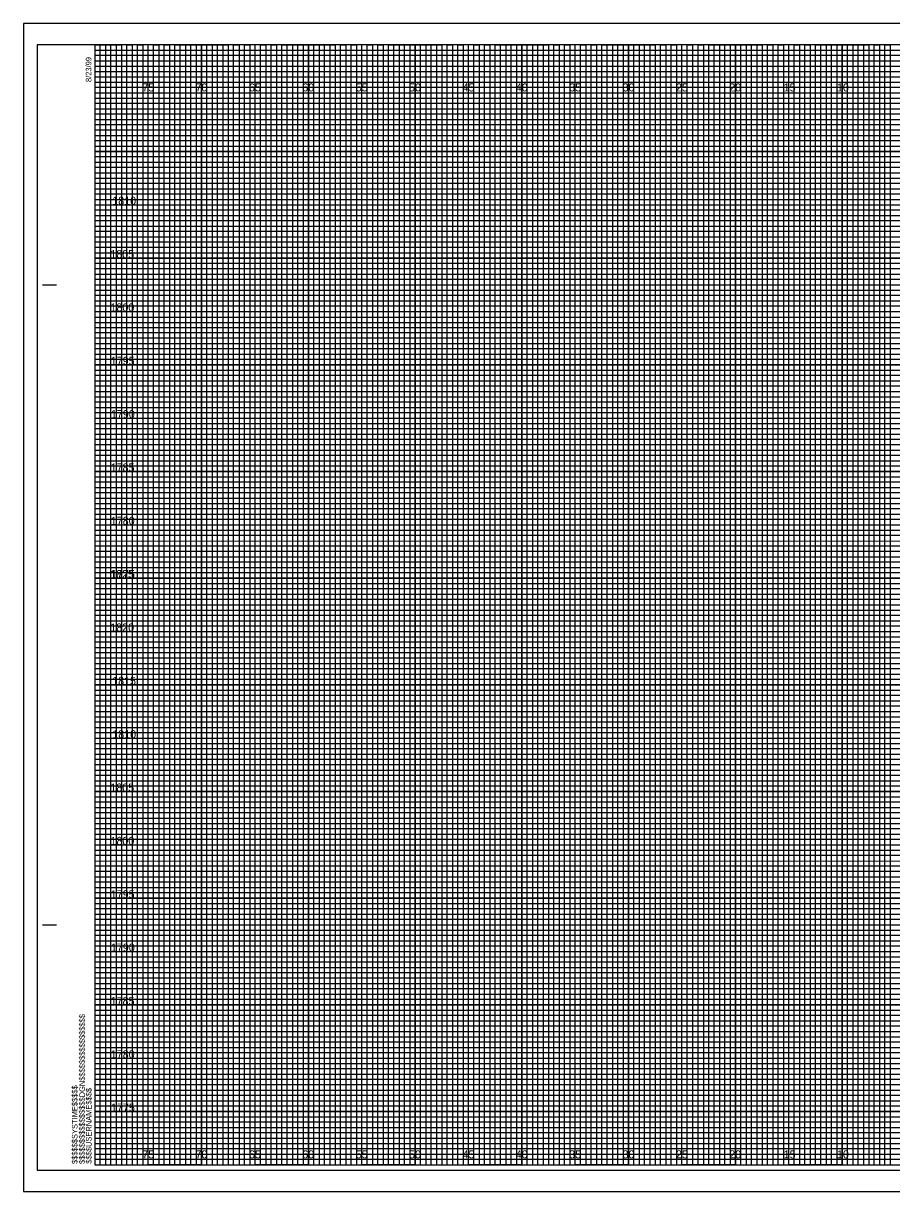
# Model space of a CAD drawing. Extents: x -7 to 162, y -2 to 107.
# Drawn here: x -6.7 to 74.6, y -2.5 to 107 of the extents above; entities that cross this region are included whole.
import ezdxf

# ---------------------------------------------------------------- set-up
doc = ezdxf.new("R2010")
doc.units = 0
for name, color, linetype in [('Prop XS Elevation Labels', 7, 'Continuous'), ('Prop XS Offset Labels', 7, 'Continuous'), ('Sheet Cross Section CELL', 7, 'Continuous'), ('Sheet Cross Section Grid Major CELL', 7, 'Continuous'), ('Sheet Cross Section Grid Middle CELL', 7, 'Continuous'), ('Sheet Cross Section Grid Minor 1 CELL', 7, 'Continuous'), ('Sheet Cross Section Grid Minor 2 CELL', 7, 'Continuous'), ('Sheet Cutting Line CELL', 7, 'Continuous'), ('Sheet DOT Grid CELL', 7, 'Continuous'), ('Sheet Plot Border Inside CELL', 7, 'Continuous'), ('Sheet Plot Border Outside CELL', 7, 'Continuous')]:
    doc.layers.add(name, color=color, linetype=linetype)

msp = doc.modelspace()

# ---------------------------------------------------------------- linework, layer by layer
at = {"layer": 'Sheet Cross Section CELL'}
for p, q in [((-4.9, 82.5), (-3.65, 82.5)), ((-4.85, 82.5), (-3.6, 82.5)), ((-4.9, 22.5), (-3.65, 22.5)), ((-4.85, 22.5), (-3.6, 22.5)), ((0, 0), (0, 0)), ((0, 0), (0, 0)), ((0, 0), (0, 0)), ((0, 0), (0, 0)), ((0, 0), (0, 0)), ((0, 0), (0, 0)), ((0, 0), (0, 0))]:
    msp.add_line(p, q, dxfattribs=at)
msp.add_lwpolyline([(160, 105), (0, 105), (0, 0), (160, 0)], close=True, dxfattribs=at)
at = {"layer": 'Sheet Cross Section Grid Major CELL'}
for p, q in [((5, 105), (0, 105)), ((5, 0), (5, 105)), ((15, 105), (10, 105)), ((10, 105), (10, 0)), ((15, 0), (15, 105)), ((25, 105), (20, 105)), ((20, 105), (20, 0)), ((25, 0), (25, 105)), ((35, 105), (30, 105)), ((30, 105), (30, 0)), ((35, 0), (35, 105)), ((45, 105), (40, 105)), ((40, 105), (40, 0)), ((45, 0), (45, 105)), ((55, 105), (50, 105)), ((50, 105), (50, 0)), ((55, 0), (55, 105)), ((65, 105), (60, 105)), ((60, 105), (60, 0)), ((65, 0), (65, 105)), ((75, 105), (70, 105)), ((70, 105), (70, 0)), ((10, 0), (5, 0)), ((20, 0), (15, 0)), ((30, 0), (25, 0)), ((40, 0), (35, 0)), ((50, 0), (45, 0)), ((60, 0), (55, 0)), ((70, 0), (65, 0))]:
    msp.add_line(p, q, dxfattribs=at)
for points in [[(0, 100), (160, 100), (160, 95), (0, 95)], [(0, 90), (160, 90), (160, 85), (0, 85)], [(0, 80), (160, 80), (160, 75), (0, 75)], [(0, 70), (160, 70), (160, 65), (0, 65)], [(0, 60), (160, 60), (160, 55), (0, 55)], [(0, 50), (160, 50), (160, 45), (0, 45)], [(0, 40), (160, 40), (160, 35), (0, 35)], [(0, 30), (160, 30), (160, 25), (0, 25)], [(0, 20), (160, 20), (160, 15), (0, 15)], [(0, 10), (160, 10), (160, 5), (0, 5)]]:
    msp.add_lwpolyline(points, dxfattribs=at)
at = {"layer": 'Sheet Cross Section Grid Middle CELL'}
for points in [[(0, 105), (2.5, 105), (2.5, 0), (7.5, 0), (7.5, 105), (12.5, 105), (12.5, 0), (17.5, 0), (17.5, 105), (22.5, 105), (22.5, 0), (27.5, 0), (27.5, 105), (32.5, 105), (32.5, 0), (37.5, 0), (37.5, 105), (42.5, 105), (42.5, 0), (47.5, 0), (47.5, 105), (52.5, 105), (52.5, 0), (57.5, 0), (57.5, 105), (62.5, 105), (62.5, 0), (67.5, 0), (67.5, 105), (72.5, 105), (72.5, 0), (77.5, 0)], [(0, 102.5), (137.5, 102.5)], [(0, 92.5), (160, 92.5), (160, 97.5), (0, 97.5)], [(0, 82.5), (160, 82.5), (160, 87.5), (0, 87.5)], [(0, 72.5), (160, 72.5), (160, 77.5), (0, 77.5)], [(0, 62.5), (160, 62.5), (160, 67.5), (0, 67.5)], [(0, 52.5), (160, 52.5), (160, 57.5), (0, 57.5)], [(0, 42.5), (160, 42.5), (160, 47.5), (0, 47.5)], [(0, 32.5), (160, 32.5), (160, 37.5), (0, 37.5)], [(0, 22.5), (160, 22.5), (160, 27.5), (0, 27.5)], [(0, 12.5), (160, 12.5), (160, 17.5), (0, 17.5)], [(0, 2.5), (160, 2.5), (160, 7.5), (0, 7.5)]]:
    msp.add_lwpolyline(points, dxfattribs=at)
at = {"layer": 'Sheet Cross Section Grid Minor 1 CELL'}
for p, q in [((0, 104.5), (130, 104.5)), ((130, 103.99), (0, 103.99)), ((0, 103.99), (0, 103.5)), ((0, 103.5), (130, 103.5)), ((130, 102.95), (0, 102.95)), ((0, 102.95), (0, 102)), ((0, 102), (160, 102))]:
    msp.add_line(p, q, dxfattribs=at)
for points in [[(0, 101.5), (135, 101.5), (160, 101.5), (160, 101), (0, 101)], [(0, 100.5), (160, 100.5), (160, 99.5), (0, 99.5)], [(0, 99), (160, 99), (160, 98.5), (0, 98.49)], [(0, 98), (160, 98), (160, 97), (0, 97)], [(0, 96.5), (160, 96.5), (160, 96), (0, 96)], [(0, 95.5), (160, 95.5), (160, 94.5), (0, 94.5)], [(0, 94), (160, 94), (160, 93.5), (0, 93.5)], [(0, 93), (160, 93), (160, 92), (0, 92)], [(0, 91.5), (160, 91.5), (160, 91), (0, 91)], [(0, 90.5), (160, 90.5), (160, 89.5), (0, 89.5)], [(0, 89), (160, 89), (160, 88.5), (0, 88.5)], [(0, 88), (160, 88), (160, 86.98), (160, 86.5), (160, 86), (0, 86)], [(0, 87), (160, 87), (160, 86.5), (0, 86.5)], [(0, 85.5), (160, 85.5), (160, 84.5), (0, 84.52)], [(0, 84.52), (160, 84.5), (160, 84), (0, 84)], [(0, 83.5), (160, 83.5), (160, 83), (0, 83)], [(0, 82), (160, 82), (160, 81.5), (0, 81.5)], [(0, 81), (160, 81), (160, 80.5), (0, 80.5)], [(-0.04, 79.45), (160, 79.45), (160, 78.94), (-0.04, 78.94)], [(0, 78.5), (160, 78.5), (160, 78), (0, 78)], [(0, 77), (160, 77), (160, 76.5), (0, 76.5)], [(0, 76), (160, 76), (160, 75.5), (0, 75.5)], [(0, 74.5), (160, 74.5), (160, 74), (0, 74)], [(0, 73.5), (160, 73.5), (160, 73), (0, 73)], [(0, 72), (160, 72), (160, 71.5), (0, 71.5)], [(0, 71), (160, 71), (160, 70.5), (0, 70.5)], [(0, 69.5), (160, 69.5), (160, 68.99), (0, 69)], [(0, 68.5), (160, 68.5), (160, 68), (0, 68)], [(0, 67), (160, 67), (160, 66.5), (0, 66.5)], [(0, 66), (160, 66), (160, 65.5), (0, 65.5)], [(0, 64.5), (160, 64.5), (160, 64), (0, 64)], [(0, 63.5), (160, 63.5), (160, 63), (0, 63)], [(0, 62), (160, 62), (160, 61.5), (0, 61.5)], [(0, 61), (160, 61), (160, 60.5), (0, 60.5)], [(0, 59.5), (160, 59.5), (160, 59), (0, 59)], [(0, 58.5), (160.03, 58.45), (160, 58), (0, 58)], [(0, 57), (160, 57), (160, 56.5), (0, 56.5)], [(0, 56), (160, 56), (160, 55.5), (0, 55.5)], [(0, 54.5), (160, 54.5), (160, 54), (0, 54)], [(0, 53.5), (160, 53.5), (160, 53), (0, 53)], [(0, 52), (160, 52), (160, 51.5), (0, 51.5)], [(0, 51), (160, 51), (160, 50.5), (0, 50.5)], [(0, 49.5), (160, 49.5), (160, 49), (0, 49)], [(0, 48.5), (160, 48.5), (160, 48), (0, 48)], [(0, 47), (160, 47), (160, 46.5), (0, 46.5)], [(0, 46), (160, 46), (160, 45.5), (0, 45.5)], [(0, 44.5), (160, 44.5), (160, 44), (0, 44)], [(0, 43.5), (160, 43.5), (160, 43), (0, 43)], [(0, 42), (160, 42), (160, 41.5), (0, 41.5)], [(0, 41), (160, 41), (160, 40.5), (0, 40.5)], [(0, 39.5), (160, 39.5), (160, 38.99), (0, 39)], [(0, 38.5), (160, 38.5), (160, 38), (0, 38)], [(0, 37), (160, 37), (160, 36.5), (0, 36.5)], [(0, 36), (160, 36), (160, 35.5), (0, 35.5)], [(0, 34.5), (160, 34.5), (160, 34), (0, 34)], [(0, 33.5), (160, 33.5), (160, 33), (0, 33)], [(0, 32), (160, 32), (160, 31.5), (0, 31.5)], [(0, 31), (160, 31), (160, 30.5), (0, 30.5)], [(0, 29.5), (160, 29.5), (160, 29), (0, 29)], [(0, 28.5), (160.03, 28.46), (160, 28), (0, 28)], [(0, 27), (160, 27), (160, 26.5), (0, 26.5)], [(0, 26), (160, 26), (160, 25.5), (0, 25.5)], [(0, 24.5), (160, 24.5), (160, 24), (0, 24)], [(0, 23.5), (160, 23.5), (160, 23), (0, 23)], [(0, 22), (160, 22), (160, 21.5), (0, 21.5)], [(0, 21), (160, 21), (160, 20.5), (0, 20.5)], [(0, 19.5), (160, 19.5), (160, 19), (0, 19)], [(0, 18.5), (160, 18.5), (160, 18), (0, 18)], [(0, 17), (160, 17), (160, 16.5), (0, 16.5)], [(0, 16), (160, 16), (160, 15.5), (0, 15.5)], [(0, 14.5), (160, 14.5), (160, 14), (0, 14)], [(0, 13.5), (160, 13.5), (160, 13), (0, 13)], [(0, 12), (160, 12), (160, 11.5), (0, 11.5)], [(0, 11), (160, 11), (160, 10.5), (0, 10.5)], [(0, 9.5), (160, 9.5), (160, 9), (0, 9)], [(0, 8.5), (160, 8.5), (160, 8), (0, 8)], [(0, 7), (160, 7), (160, 6.5), (0, 6.5)], [(0, 6), (160, 6), (160, 5.5), (0, 5.5)], [(0, 4.5), (160, 4.5), (160, 4), (0, 4)], [(0, 3.5), (160, 3.5), (160, 3), (0, 3)], [(0, 2), (160, 2), (160, 1.5), (0, 1.5)], [(0, 1), (160, 1), (160, 0.5), (0, 0.5)]]:
    msp.add_lwpolyline(points, dxfattribs=at)
at = {"layer": 'Sheet Cross Section Grid Minor 2 CELL'}
for points in [[(0, 0), (0.5, 0), (0.5, 105), (1, 105), (1, 0)], [(1, 0), (1.5, 0), (1.5, 105), (2, 105), (2, 0)], [(2.5, 0), (3, 0), (3, 105), (3.5, 105), (3.5, 0)], [(3.5, 0), (4, 0), (4, 105), (4.5, 105), (4.5, 0)], [(5, 0), (5.5, 0), (5.5, 105), (6, 105), (6, 0)], [(6, 0), (6.5, 0), (6.5, 105), (7, 105), (7, 0)], [(7.5, 0), (8, 0), (8, 105), (8.5, 105), (8.5, 0)], [(8.5, 0), (9, 0), (9, 105), (9.5, 105), (9.5, 0)], [(10, 0), (10.5, 0), (10.5, 105), (11, 105), (11, 0)], [(11, 0), (11.5, 0), (11.5, 105), (12, 105), (12, 0)], [(12.5, 0), (13, 0), (13, 105), (13.5, 105), (13.5, 0)], [(13.5, 0), (14, 0), (14, 105), (14.5, 105), (14.5, 0)], [(15, 0), (15.5, 0), (15.5, 105), (16, 105), (16, 0)], [(16, 0), (16.5, 0), (16.5, 105), (17, 105), (17, 0)], [(17.5, 0), (18, 0), (18, 105), (18.5, 105), (18.5, 0)], [(18.5, 0), (19, 0), (19, 105), (19.5, 105), (19.5, 0)], [(20, 0), (20.5, 0), (20.5, 105), (21, 105), (21, 0)], [(21, 0), (21.5, 0), (21.5, 105), (22, 105), (22, 0)], [(22.5, 0), (23, 0), (23, 105), (23.5, 105), (23.5, 0)], [(23.5, 0), (24, 0), (24, 105), (24.5, 105), (24.5, 0)], [(25, 0), (25.5, 0), (25.5, 105), (26, 105), (26, 0)], [(26, 0), (26.5, 0), (26.5, 105), (27, 105), (27, 0)], [(27.5, 0), (28, 0), (28, 105), (28.5, 105), (28.5, 0)], [(28.5, 0), (29, 0), (29, 105), (29.5, 105), (29.5, 0)], [(30, 0), (30.5, 0), (30.5, 105), (31, 105), (31, 0)], [(31, 0), (31.5, 0), (31.5, 105), (32, 105), (32, 0)], [(32.5, 0), (33, 0), (33, 105), (33.5, 105), (33.5, 0)], [(33.5, 0), (34, 0), (34, 105), (34.5, 105), (34.5, 0)], [(35, 0), (35.5, 0), (35.5, 105), (36, 105), (36, 0)], [(36, 0), (36.5, 0), (36.5, 105), (37, 105), (37, 0)], [(37.5, 0), (38, 0), (38, 105), (38.5, 105), (38.5, 0)], [(38.5, 0), (39, 0), (39, 105), (39.5, 105), (39.5, 0)], [(40, 0), (40.5, 0), (40.5, 105), (41, 105), (41, 0)], [(41, 0), (41.5, 0), (41.5, 105), (42, 105), (42, 0)], [(42.5, 0), (43, 0), (43, 105), (43.5, 105), (43.5, 0)], [(43.5, 0), (44, 0), (44, 105), (44.5, 105), (44.5, 0)], [(45, 0), (45.5, 0), (45.5, 105), (46, 105), (46, 0)], [(46, 0), (46.5, 0), (46.5, 105), (47, 105), (47, 0)], [(47.5, 0), (48, 0), (48, 105), (48.5, 105), (48.5, 0)], [(48.5, 0), (49, 0), (49, 105), (49.5, 105), (49.5, 0)], [(50, 0), (50.5, 0), (50.5, 105), (51, 105), (51, 0)], [(51, 0), (51.5, 0), (51.5, 105), (52, 105), (52, 0)], [(52.5, 0), (53, 0), (53, 105), (53.5, 105), (53.5, 0)], [(53.5, 0), (54, 0), (54, 105), (54.5, 105), (54.5, 0)], [(55, 0), (55.5, 0), (55.5, 105), (56, 105), (56, 0)], [(56, 0), (56.5, 0), (56.5, 105), (57, 105), (57, 0)], [(57.5, 0), (58, 0), (58, 105), (58.5, 105), (58.5, 0)], [(58.5, 0), (59, 0), (59, 105), (59.5, 105), (59.5, 0)], [(60, 0), (60.5, 0), (60.5, 105), (61, 105), (61, 0)], [(61, 0), (61.5, 0), (61.5, 105), (62, 105), (62, 0)], [(62.5, 0), (63, 0), (63, 105), (63.5, 105), (63.5, 0)], [(63.5, 0), (64, 0), (64, 105), (64.5, 105), (64.5, 0)], [(65, 0), (65.5, 0), (65.5, 105), (66, 105), (66, 0)], [(66, 0), (66.5, 0), (66.5, 105), (67, 105), (67, 0)], [(67.5, 0), (68, 0), (68, 105), (68.5, 105), (68.5, 0)], [(68.5, 0), (69, 0), (69, 105), (69.5, 105), (69.5, 0)], [(70, 0), (70.5, 0), (70.5, 105), (71, 105), (71, 0)], [(71, 0), (71.5, 0), (71.5, 105), (72, 105), (72, 0)], [(72.5, 0), (73, 0), (73, 105), (73.5, 105), (73.5, 0)], [(73.5, 0), (74, 0), (74, 105), (74.5, 105), (74.5, 0)]]:
    msp.add_lwpolyline(points, dxfattribs=at)
at = {"layer": 'Sheet Cutting Line CELL'}
for p, q in [((161.65, 107), (-6.7, 107)), ((-6.7, 107), (-6.7, -2.5)), ((-6.7, -2.5), (161.65, -2.5))]:
    msp.add_line(p, q, dxfattribs=at)
at = {"layer": 'Sheet DOT Grid CELL'}
for p, q in [((5, 0), (5, 105)), ((10, 0), (10, 105)), ((15, 0), (15, 105)), ((20, 0), (20, 105)), ((25, 0), (25, 105)), ((30, 0), (30, 105)), ((35, 0), (35, 105)), ((40, 0), (40, 105)), ((45, 0), (45, 105)), ((50, 0), (50, 105)), ((55, 0), (55, 105)), ((60, 0), (60, 105)), ((65, 0), (65, 105)), ((70, 0), (70, 105)), ((0, 100), (160, 100)), ((0, 95), (160, 95)), ((0, 90), (160, 90)), ((0, 85), (160, 85)), ((0, 80), (160, 80)), ((0, 75), (160, 75)), ((0, 70), (160, 70)), ((0, 65), (160, 65)), ((0, 60), (160, 60)), ((0, 55), (160, 55)), ((0, 50), (160, 50)), ((0, 45), (160, 45)), ((0, 40), (160, 40)), ((0, 35), (160, 35)), ((0, 30), (160, 30)), ((0, 25), (160, 25)), ((0, 20), (160, 20)), ((0, 15), (160, 15)), ((0, 10), (160, 10)), ((0, 5), (160, 5))]:
    msp.add_line(p, q, dxfattribs=at)
at = {"layer": 'Sheet Plot Border Inside CELL'}
msp.add_lwpolyline([(-5.4, -0.5), (161.2, -0.5), (161.2, 105), (-5.4, 105)], close=True, dxfattribs=at)
at = {"layer": 'Sheet Plot Border Outside CELL'}
msp.add_lwpolyline([(-6.7, -2.5), (161.65, -2.5), (161.65, 107), (-6.7, 107)], close=True, dxfattribs=at)

# ---------------------------------------------------------------- texts
at = {"layer": 'Prop XS Elevation Labels'}
for s, p in [('1810', (1.63, 90)), ('1805', (1.45, 85)), ('1800', (1.46, 80)), ('1795', (1.49, 75)), ('1790', (1.5, 70)), ('1785', (1.48, 65)), ('1780', (1.49, 60)), ('1825', (1.43, 55)), ('1775', (1.51, 55)), ('1820', (1.44, 50)), ('1815', (1.62, 45)), ('1810', (1.63, 40)), ('1805', (1.45, 35)), ('1800', (1.46, 30)), ('1795', (1.49, 25)), ('1790', (1.5, 20)), ('1785', (1.48, 15)), ('1780', (1.49, 10)), ('1775', (1.51, 5))]:
    msp.add_text(s, height=0.75, dxfattribs=at).set_placement(p)
at = {"layer": 'Prop XS Offset Labels'}
for s, p in [('75', (4.44, 100.62)), ('70', (9.43, 100.62)), ('65', (14.44, 100.62)), ('60', (19.43, 100.62)), ('55', (24.44, 100.62)), ('50', (29.43, 100.62)), ('45', (34.44, 100.62)), ('40', (39.43, 100.62)), ('35', (44.44, 100.62)), ('30', (49.43, 100.62)), ('25', (54.44, 100.62)), ('20', (59.43, 100.62)), ('15', (64.53, 100.62)), ('10', (69.52, 100.62)), ('75', (4.44, 0.62)), ('70', (9.43, 0.62)), ('65', (14.44, 0.62)), ('60', (19.43, 0.62)), ('55', (24.44, 0.62)), ('50', (29.43, 0.62)), ('45', (34.44, 0.62)), ('40', (39.43, 0.62)), ('35', (44.44, 0.62)), ('30', (49.43, 0.62)), ('25', (54.44, 0.62)), ('20', (59.43, 0.62)), ('15', (64.53, 0.62)), ('10', (69.52, 0.62))]:
    msp.add_text(s, height=0.75, dxfattribs=at).set_placement(p)
at = {"layer": 'Sheet Cross Section CELL'}
for s, p in [('8/23/99', (-0.33, 101.5)), ('$$$$$$$$$$$$$$$$DGN$$$$$$$$$$$$$$$$', (-0.94, 0.09)), ('$$$$$$SYSTIME$$$$$', (-1.63, 0.09)), ('$$$$USERNAME$$$$', (-0.31, 0.12))]:
    msp.add_text(s, height=0.525, rotation=90, dxfattribs=at).set_placement(p)

doc.saveas('drawing.dxf')
